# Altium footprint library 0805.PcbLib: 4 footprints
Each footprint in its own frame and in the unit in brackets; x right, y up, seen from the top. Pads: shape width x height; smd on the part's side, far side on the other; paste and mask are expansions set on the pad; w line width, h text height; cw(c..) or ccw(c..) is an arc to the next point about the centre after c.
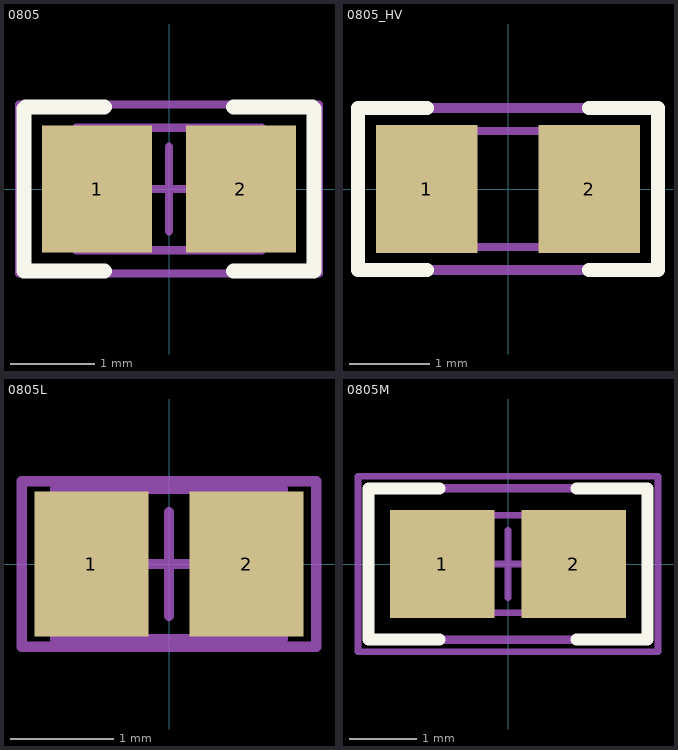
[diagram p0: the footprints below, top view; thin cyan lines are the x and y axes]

## 0805 [mm] "0805 from SM-752 data"
height 1.1
pads (2):
  rect 1.3x1.5 smd: 1(-0.85,0) 2(0.85,0)
Top Overlay:
  lines w0.178: -0.762,-0.968 -1.717,-0.968 -1.717,0.95 -1.699,0.968 -0.762,0.968 ; 0.762,-0.968 1.717,-0.968 1.717,0.95 1.699,0.968 0.762,0.968
M5 Assembly Top:
  lines w0.1: -1.775,-1 1.775,-1 1.775,1 -1.775,1 -1.775,-1
  text ".Designator" at -1.525,-0.425 h0.81
M13 Component Bodies Top:
  lines w0.1: -0.65,-0.725 -0.65,0.725 ; 0.65,-0.725 0.65,0.725 ; -1.1,-0.725 1.1,-0.725 1.1,0.725 -1.1,0.725 -1.1,-0.725
M15  Courtyards Top:
  lines w0.1: -0.5,0 0.5,0 ; 0,-0.5 0,0.5 ; -1.775,-1 1.775,-1 1.775,1 -1.775,1 -1.775,-1
3D body: height 1.1, standoff 0, extent -1.099,-0.724 -0.651,0.724
3D body: height 1.1, standoff 0, extent -0.649,-0.724 0.649,0.724
3D body: height 1.1, standoff 0, extent 0.651,-0.724 1.099,0.724

## 0805_HV [mil] "0805 with 30mil clearance between pads"
height 43.31
pads (2):
  rect 50x63 smd: 1(-40,0) 2(40,0)
Top Overlay:
  lines w7: -40,-40 -74,-40 -74,0 -74,40 -40,40 ; 40,-40 74,-40 74,0 74,40 40,40
M5 Assembly Top:
  lines w5: -74,-40 74,-40 74,40 -74,40 -74,-40
  text ".Designator" at -64,-17 h35
M13 Component Bodies Top:
  lines w3.94: -25.59,-28.54 -25.59,28.54 ; 25.59,-28.54 25.59,28.54 ; -43.31,-28.54 -43.31,28.54 43.31,28.54 43.31,-28.54 -43.31,-28.54
3D body: height 43.31, standoff 0, extent 25.61,-28.52 43.29,28.52
3D body: height 43.31, standoff 0, extent -25.57,-28.52 25.57,28.52
3D body: height 43.31, standoff 0, extent -43.29,-28.52 -25.61,28.52

## 0805L [mm] "0805 from SM-752 data"
height 1.1
pads (2):
  rect 1.1x1.4 smd: 1(-0.75,0) 2(0.75,0)
M5 Assembly Top:
  lines w0.1: -1.425,-0.8 1.425,-0.8 1.425,0.8 -1.425,0.8 -1.425,-0.8
  text ".Designator" at -1.2,-0.325 h0.64
M13 Component Bodies Top:
  lines w0.1: -0.65,-0.725 -0.65,0.725 ; 0.65,-0.725 0.65,0.725 ; -1.1,-0.725 1.1,-0.725 1.1,0.725 -1.1,0.725 -1.1,-0.725
M15  Courtyards Top:
  lines w0.1: -0.5,0 0.5,0 ; 0,-0.5 0,0.5 ; -1.425,-0.8 -1.425,0.8 1.425,0.8 1.425,-0.8 -1.425,-0.8
3D body: height 1.1, standoff 0, extent -1.099,-0.724 -0.651,0.724
3D body: height 1.1, standoff 0, extent -0.649,-0.724 0.649,0.724
3D body: height 1.1, standoff 0, extent 0.651,-0.724 1.099,0.724

## 0805M [mm] "0805 from SM-752 data"
height 1.1
pads (2):
  rect 1.55x1.6 smd: 1(-0.975,0) 2(0.975,0)
Top Overlay:
  lines w0.178: -1.016,-1.118 -2.068,-1.118 -2.068,1.118 -1.016,1.118 ; 1.016,-1.118 2.068,-1.118 2.068,1.118 1.016,1.118
M5 Assembly Top:
  lines w0.127: -2.075,-1.125 -2.075,1.125 2.075,1.125 2.075,-1.125 -2.075,-1.125
  text ".Designator" at -1.862,-0.508 h1.02
M13 Component Bodies Top:
  lines w0.1: -0.65,-0.725 -0.65,0.725 ; 0.65,-0.725 0.65,0.725 ; -1.1,-0.725 1.1,-0.725 1.1,0.725 -1.1,0.725 -1.1,-0.725
M15  Courtyards Top:
  lines w0.1: -0.5,0 0.5,0 ; 0,-0.5 0,0.5 ; -2.225,-1.3 2.225,-1.3 2.225,1.3 -2.225,1.3 -2.225,-1.3
3D body: height 1.1, standoff 0, extent -1.099,-0.724 -0.651,0.724
3D body: height 1.1, standoff 0, extent -0.649,-0.724 0.649,0.724
3D body: height 1.1, standoff 0, extent 0.651,-0.724 1.099,0.724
